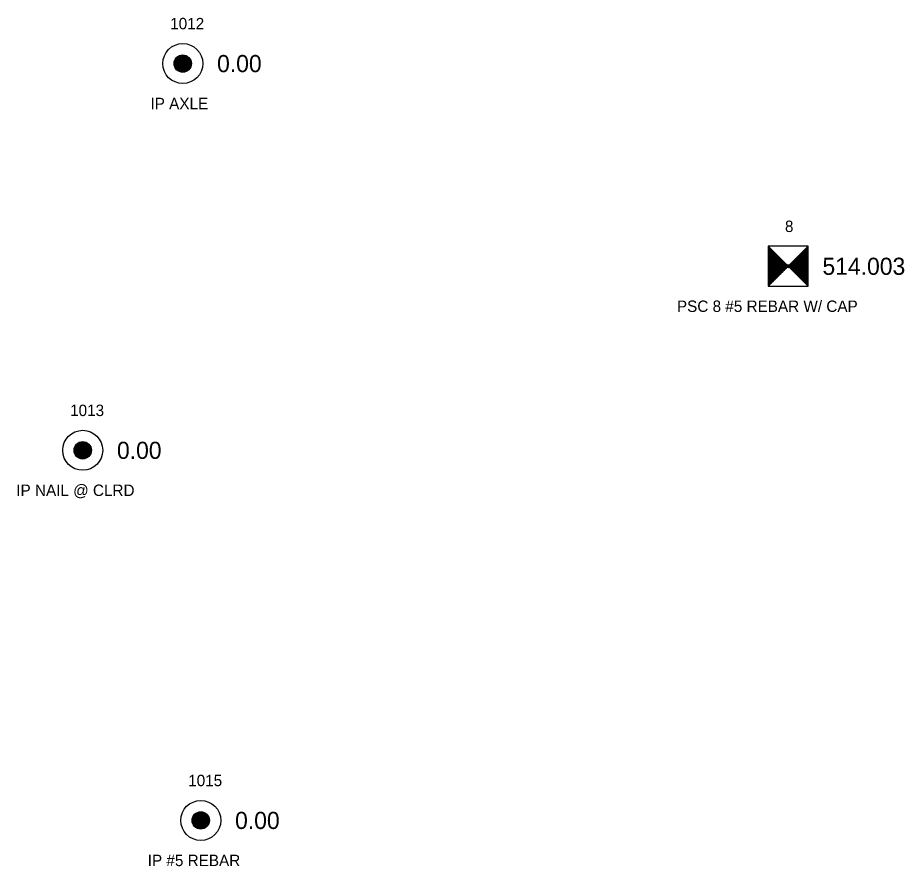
# Model space of a CAD drawing. Extents: x 1784103 to 1787401, y 770251 to 771298.
# Drawn here: x 1787322.9 to 1787400.5, y 770869.4 to 770943.7 of the extents above; entities that cross this region are included whole.
import ezdxf

# ---------------------------------------------------------------- set-up
doc = ezdxf.new("R2010")
doc.units = 0
for name, color, linetype in [('RD_EX_DV_Prop_txCode', 7, 'Continuous'), ('RD_EX_DV_PropPin', 7, 'Continuous'), ('RD_EX_TX_DV_Prop_ELEV', 7, 'Continuous'), ('RD_HC_Survey', 7, 'Continuous'), ('RD_HC_Survey_ELEV', 7, 'Continuous'), ('RD_HC_txCode', 7, 'Continuous'), ('RD_SMD_Locator', 7, 'Continuous')]:
    doc.layers.add(name, color=color, linetype=linetype)

msp = doc.modelspace()

# ---------------------------------------------------------------- linework, layer by layer
at = {"layer": 'RD_EX_DV_PropPin'}
for p, q in [((1787336.678, 770939.403), (1787336.678, 770939.999)), ((1787336.713, 770939.331), (1787336.713, 770940.07)), ((1787336.748, 770939.274), (1787336.748, 770940.127)), ((1787336.783, 770939.226), (1787336.783, 770940.175)), ((1787336.818, 770939.186), (1787336.818, 770940.216)), ((1787336.853, 770939.15), (1787336.853, 770940.251)), ((1787336.888, 770939.118), (1787336.888, 770940.283)), ((1787336.923, 770939.091), (1787336.923, 770940.31)), ((1787336.958, 770939.066), (1787336.958, 770940.335)), ((1787336.993, 770939.044), (1787336.993, 770940.357)), ((1787337.028, 770939.025), (1787337.028, 770940.376)), ((1787337.063, 770939.008), (1787337.063, 770940.393)), ((1787337.098, 770938.993), (1787337.098, 770940.408)), ((1787337.133, 770938.98), (1787337.133, 770940.421)), ((1787337.168, 770938.969), (1787337.168, 770940.432)), ((1787337.203, 770938.96), (1787337.203, 770940.441)), ((1787337.238, 770938.953), (1787337.238, 770940.449)), ((1787337.273, 770938.947), (1787337.273, 770940.454)), ((1787337.308, 770938.943), (1787337.308, 770940.458)), ((1787337.343, 770938.94), (1787337.343, 770940.461)), ((1787337.378, 770938.94), (1787337.378, 770940.462)), ((1787337.413, 770938.94), (1787337.413, 770940.461)), ((1787337.449, 770938.943), (1787337.449, 770940.458)), ((1787337.484, 770938.947), (1787337.484, 770940.454)), ((1787337.519, 770938.953), (1787337.519, 770940.449)), ((1787337.554, 770938.96), (1787337.554, 770940.441)), ((1787337.589, 770938.969), (1787337.589, 770940.432)), ((1787337.624, 770938.98), (1787337.624, 770940.421)), ((1787337.659, 770938.993), (1787337.659, 770940.408)), ((1787337.694, 770939.008), (1787337.694, 770940.393)), ((1787337.729, 770939.025), (1787337.729, 770940.376)), ((1787337.764, 770939.044), (1787337.764, 770940.357)), ((1787337.799, 770939.066), (1787337.799, 770940.335)), ((1787337.834, 770939.091), (1787337.834, 770940.31)), ((1787337.869, 770939.118), (1787337.869, 770940.283)), ((1787337.904, 770939.15), (1787337.904, 770940.251)), ((1787337.939, 770939.186), (1787337.939, 770940.216)), ((1787337.974, 770939.226), (1787337.974, 770940.175)), ((1787338.009, 770939.274), (1787338.009, 770940.127)), ((1787338.044, 770939.331), (1787338.044, 770940.07)), ((1787338.079, 770939.403), (1787338.079, 770939.999)), ((1787336.643, 770939.504), (1787336.643, 770939.897)), ((1787338.114, 770939.504), (1787338.114, 770939.897)), ((1787327.88, 770905.633), (1787327.88, 770906.025)), ((1787327.915, 770905.531), (1787327.915, 770906.127)), ((1787327.95, 770905.459), (1787327.95, 770906.198)), ((1787327.985, 770905.402), (1787327.985, 770906.255)), ((1787328.02, 770905.355), (1787328.02, 770906.303)), ((1787328.055, 770905.314), (1787328.055, 770906.344)), ((1787328.09, 770905.278), (1787328.09, 770906.379)), ((1787328.125, 770905.247), (1787328.125, 770906.411)), ((1787328.16, 770905.219), (1787328.16, 770906.439)), ((1787328.195, 770905.194), (1787328.195, 770906.463)), ((1787328.23, 770905.172), (1787328.23, 770906.485)), ((1787328.265, 770905.153), (1787328.265, 770906.504)), ((1787328.3, 770905.136), (1787328.3, 770906.521)), ((1787328.335, 770905.121), (1787328.335, 770906.536)), ((1787328.37, 770905.108), (1787328.37, 770906.549)), ((1787328.405, 770905.097), (1787328.405, 770906.56)), ((1787328.44, 770905.088), (1787328.44, 770906.569)), ((1787328.475, 770905.081), (1787328.475, 770906.577)), ((1787328.51, 770905.075), (1787328.51, 770906.582)), ((1787328.545, 770905.071), (1787328.545, 770906.586)), ((1787328.58, 770905.068), (1787328.58, 770906.589)), ((1787328.615, 770905.068), (1787328.615, 770906.59)), ((1787328.65, 770905.068), (1787328.65, 770906.589)), ((1787328.685, 770905.071), (1787328.685, 770906.586)), ((1787328.72, 770905.075), (1787328.72, 770906.582)), ((1787328.755, 770905.081), (1787328.755, 770906.577)), ((1787328.79, 770905.088), (1787328.79, 770906.569)), ((1787328.825, 770905.097), (1787328.825, 770906.56)), ((1787328.86, 770905.108), (1787328.86, 770906.549)), ((1787328.895, 770905.121), (1787328.895, 770906.536)), ((1787328.93, 770905.136), (1787328.93, 770906.521)), ((1787328.965, 770905.153), (1787328.965, 770906.504)), ((1787329, 770905.172), (1787329, 770906.485)), ((1787329.035, 770905.194), (1787329.035, 770906.463)), ((1787329.07, 770905.219), (1787329.07, 770906.439)), ((1787329.105, 770905.247), (1787329.105, 770906.411)), ((1787329.14, 770905.278), (1787329.14, 770906.379)), ((1787329.175, 770905.314), (1787329.175, 770906.344)), ((1787329.21, 770905.355), (1787329.21, 770906.303)), ((1787329.245, 770905.402), (1787329.245, 770906.255)), ((1787329.28, 770905.459), (1787329.28, 770906.198)), ((1787329.315, 770905.531), (1787329.315, 770906.127)), ((1787329.35, 770905.633), (1787329.35, 770906.025)), ((1787338.464, 770872.831), (1787338.464, 770873.995)), ((1787338.499, 770872.803), (1787338.499, 770874.023)), ((1787338.534, 770872.778), (1787338.534, 770874.048)), ((1787338.569, 770872.757), (1787338.569, 770874.069)), ((1787338.604, 770872.737), (1787338.604, 770874.089)), ((1787338.639, 770872.72), (1787338.639, 770874.106)), ((1787338.674, 770872.705), (1787338.674, 770874.121)), ((1787338.709, 770872.693), (1787338.709, 770874.133)), ((1787338.744, 770872.682), (1787338.744, 770874.144)), ((1787338.779, 770872.672), (1787338.779, 770874.154)), ((1787338.814, 770872.665), (1787338.814, 770874.161)), ((1787338.849, 770872.659), (1787338.849, 770874.167)), ((1787338.884, 770872.655), (1787338.884, 770874.171)), ((1787338.919, 770872.653), (1787338.919, 770874.173)), ((1787338.954, 770872.652), (1787338.954, 770874.174)), ((1787338.989, 770872.653), (1787338.989, 770874.173)), ((1787339.025, 770872.655), (1787339.025, 770874.171)), ((1787339.06, 770872.659), (1787339.06, 770874.167)), ((1787339.095, 770872.665), (1787339.095, 770874.161)), ((1787339.13, 770872.672), (1787339.13, 770874.154)), ((1787339.165, 770872.682), (1787339.165, 770874.144)), ((1787339.2, 770872.693), (1787339.2, 770874.133)), ((1787339.235, 770872.705), (1787339.235, 770874.121)), ((1787339.27, 770872.72), (1787339.27, 770874.106)), ((1787339.305, 770872.737), (1787339.305, 770874.089)), ((1787339.34, 770872.757), (1787339.34, 770874.069)), ((1787339.375, 770872.778), (1787339.375, 770874.048)), ((1787339.41, 770872.803), (1787339.41, 770874.023)), ((1787339.445, 770872.831), (1787339.445, 770873.995)), ((1787338.219, 770873.217), (1787338.219, 770873.609)), ((1787338.254, 770873.115), (1787338.254, 770873.711)), ((1787338.289, 770873.043), (1787338.289, 770873.783)), ((1787338.324, 770872.986), (1787338.324, 770873.84)), ((1787338.359, 770872.939), (1787338.359, 770873.887)), ((1787338.394, 770872.898), (1787338.394, 770873.928)), ((1787338.429, 770872.862), (1787338.429, 770873.964)), ((1787339.48, 770872.862), (1787339.48, 770873.964)), ((1787339.515, 770872.898), (1787339.515, 770873.928)), ((1787339.55, 770872.939), (1787339.55, 770873.887)), ((1787339.585, 770872.986), (1787339.585, 770873.84)), ((1787339.62, 770873.043), (1787339.62, 770873.783)), ((1787339.655, 770873.115), (1787339.655, 770873.711)), ((1787339.69, 770873.217), (1787339.69, 770873.609))]:
    msp.add_line(p, q, dxfattribs=at)
for centre, radius in [((1787337.378, 770939.701), 1.75), ((1787337.378, 770939.701), 0.761), ((1787328.615, 770905.829), 1.75), ((1787328.615, 770905.829), 0.761), ((1787338.954, 770873.413), 1.75), ((1787338.954, 770873.413), 0.761)]:
    msp.add_circle(centre, radius, dxfattribs=at)
at = {"layer": 'RD_HC_Survey'}
for p, q in [((1787388.629, 770923.698), (1787392.129, 770920.198)), ((1787392.129, 770923.698), (1787388.629, 770920.198)), ((1787388.654, 770923.673), (1787388.654, 770920.222)), ((1787392.105, 770923.673), (1787392.105, 770920.222)), ((1787388.679, 770923.648), (1787388.679, 770920.247)), ((1787388.704, 770923.623), (1787388.704, 770920.272)), ((1787388.728, 770923.599), (1787388.728, 770920.297)), ((1787388.753, 770923.574), (1787388.753, 770920.321)), ((1787388.778, 770923.549), (1787388.778, 770920.346)), ((1787388.803, 770923.524), (1787388.803, 770920.371)), ((1787388.827, 770923.5), (1787388.827, 770920.396)), ((1787388.852, 770923.475), (1787388.852, 770920.42)), ((1787388.877, 770923.45), (1787388.877, 770920.445)), ((1787388.902, 770923.425), (1787388.902, 770920.47)), ((1787388.926, 770923.401), (1787388.926, 770920.495)), ((1787388.951, 770923.376), (1787388.951, 770920.519)), ((1787388.976, 770923.351), (1787388.976, 770920.544)), ((1787389.001, 770923.326), (1787389.001, 770920.569)), ((1787389.025, 770923.302), (1787389.025, 770920.594)), ((1787389.05, 770923.277), (1787389.05, 770920.618)), ((1787389.075, 770923.252), (1787389.075, 770920.643)), ((1787389.1, 770923.227), (1787389.1, 770920.668)), ((1787389.124, 770923.203), (1787389.124, 770920.693)), ((1787389.149, 770923.178), (1787389.149, 770920.717)), ((1787389.174, 770923.153), (1787389.174, 770920.742)), ((1787389.199, 770923.128), (1787389.199, 770920.767)), ((1787389.223, 770923.104), (1787389.223, 770920.792)), ((1787389.248, 770923.079), (1787389.248, 770920.816)), ((1787389.273, 770923.054), (1787389.273, 770920.841)), ((1787389.298, 770923.029), (1787389.298, 770920.866)), ((1787389.322, 770923.005), (1787389.322, 770920.891)), ((1787389.347, 770922.98), (1787389.347, 770920.915)), ((1787389.372, 770922.955), (1787389.372, 770920.94)), ((1787389.397, 770922.93), (1787389.397, 770920.965)), ((1787389.421, 770922.906), (1787389.421, 770920.99)), ((1787391.337, 770922.906), (1787391.337, 770920.99)), ((1787391.362, 770922.93), (1787391.362, 770920.965)), ((1787391.387, 770922.955), (1787391.387, 770920.94)), ((1787391.412, 770922.98), (1787391.412, 770920.915)), ((1787391.436, 770923.005), (1787391.436, 770920.891)), ((1787391.461, 770923.029), (1787391.461, 770920.866)), ((1787391.486, 770923.054), (1787391.486, 770920.841)), ((1787391.511, 770923.079), (1787391.511, 770920.816)), ((1787391.535, 770923.104), (1787391.535, 770920.792)), ((1787391.56, 770923.128), (1787391.56, 770920.767)), ((1787391.585, 770923.153), (1787391.585, 770920.742)), ((1787391.61, 770923.178), (1787391.61, 770920.717)), ((1787391.634, 770923.203), (1787391.634, 770920.693)), ((1787391.659, 770923.227), (1787391.659, 770920.668)), ((1787391.684, 770923.252), (1787391.684, 770920.643)), ((1787391.709, 770923.277), (1787391.709, 770920.618)), ((1787391.733, 770923.302), (1787391.733, 770920.594)), ((1787391.758, 770923.326), (1787391.758, 770920.569)), ((1787391.783, 770923.351), (1787391.783, 770920.544)), ((1787391.808, 770923.376), (1787391.808, 770920.519)), ((1787391.832, 770923.401), (1787391.832, 770920.495)), ((1787391.857, 770923.425), (1787391.857, 770920.47)), ((1787391.882, 770923.45), (1787391.882, 770920.445)), ((1787391.907, 770923.475), (1787391.907, 770920.42)), ((1787391.931, 770923.5), (1787391.931, 770920.396)), ((1787391.956, 770923.524), (1787391.956, 770920.371)), ((1787391.981, 770923.549), (1787391.981, 770920.346)), ((1787392.006, 770923.574), (1787392.006, 770920.321)), ((1787392.03, 770923.599), (1787392.03, 770920.297)), ((1787392.055, 770923.623), (1787392.055, 770920.272)), ((1787392.08, 770923.648), (1787392.08, 770920.247)), ((1787389.446, 770922.881), (1787389.446, 770921.014)), ((1787389.471, 770922.856), (1787389.471, 770921.039)), ((1787389.496, 770922.831), (1787389.496, 770921.064)), ((1787389.52, 770922.807), (1787389.52, 770921.089)), ((1787389.545, 770922.782), (1787389.545, 770921.113)), ((1787389.57, 770922.757), (1787389.57, 770921.138)), ((1787389.595, 770922.732), (1787389.595, 770921.163)), ((1787389.619, 770922.708), (1787389.619, 770921.188)), ((1787389.644, 770922.683), (1787389.644, 770921.212)), ((1787389.669, 770922.658), (1787389.669, 770921.237)), ((1787389.693, 770922.633), (1787389.693, 770921.262)), ((1787389.718, 770922.609), (1787389.718, 770921.287)), ((1787389.743, 770922.584), (1787389.743, 770921.311)), ((1787389.768, 770922.559), (1787389.768, 770921.336)), ((1787389.792, 770922.534), (1787389.792, 770921.361)), ((1787389.817, 770922.51), (1787389.817, 770921.386)), ((1787389.842, 770922.485), (1787389.842, 770921.41)), ((1787389.867, 770922.46), (1787389.867, 770921.435)), ((1787389.891, 770922.435), (1787389.891, 770921.46)), ((1787389.916, 770922.411), (1787389.916, 770921.485)), ((1787389.941, 770922.386), (1787389.941, 770921.509)), ((1787389.966, 770922.361), (1787389.966, 770921.534)), ((1787389.99, 770922.336), (1787389.99, 770921.559)), ((1787390.015, 770922.312), (1787390.015, 770921.584)), ((1787390.04, 770922.287), (1787390.04, 770921.608)), ((1787390.065, 770922.262), (1787390.065, 770921.633)), ((1787390.089, 770922.237), (1787390.089, 770921.658)), ((1787390.114, 770922.213), (1787390.114, 770921.683)), ((1787390.139, 770922.188), (1787390.139, 770921.707)), ((1787390.164, 770922.163), (1787390.164, 770921.732)), ((1787390.188, 770922.138), (1787390.188, 770921.757)), ((1787390.213, 770922.114), (1787390.213, 770921.782)), ((1787390.545, 770922.114), (1787390.545, 770921.782)), ((1787390.57, 770922.138), (1787390.57, 770921.757)), ((1787390.595, 770922.163), (1787390.595, 770921.732)), ((1787390.62, 770922.188), (1787390.62, 770921.707)), ((1787390.644, 770922.213), (1787390.644, 770921.683)), ((1787390.669, 770922.237), (1787390.669, 770921.658)), ((1787390.694, 770922.262), (1787390.694, 770921.633)), ((1787390.719, 770922.287), (1787390.719, 770921.608)), ((1787390.743, 770922.312), (1787390.743, 770921.584)), ((1787390.768, 770922.336), (1787390.768, 770921.559)), ((1787390.793, 770922.361), (1787390.793, 770921.534)), ((1787390.818, 770922.386), (1787390.818, 770921.509)), ((1787390.842, 770922.411), (1787390.842, 770921.485)), ((1787390.867, 770922.435), (1787390.867, 770921.46)), ((1787390.892, 770922.46), (1787390.892, 770921.435)), ((1787390.917, 770922.485), (1787390.917, 770921.41)), ((1787390.941, 770922.51), (1787390.941, 770921.386)), ((1787390.966, 770922.534), (1787390.966, 770921.361)), ((1787390.991, 770922.559), (1787390.991, 770921.336)), ((1787391.016, 770922.584), (1787391.016, 770921.311)), ((1787391.04, 770922.609), (1787391.04, 770921.287)), ((1787391.065, 770922.633), (1787391.065, 770921.262)), ((1787391.09, 770922.658), (1787391.09, 770921.237)), ((1787391.115, 770922.683), (1787391.115, 770921.212)), ((1787391.139, 770922.708), (1787391.139, 770921.188)), ((1787391.164, 770922.732), (1787391.164, 770921.163)), ((1787391.189, 770922.757), (1787391.189, 770921.138)), ((1787391.214, 770922.782), (1787391.214, 770921.113)), ((1787391.238, 770922.807), (1787391.238, 770921.089)), ((1787391.263, 770922.831), (1787391.263, 770921.064)), ((1787391.288, 770922.856), (1787391.288, 770921.039)), ((1787391.313, 770922.881), (1787391.313, 770921.014)), ((1787390.238, 770922.089), (1787390.238, 770921.806)), ((1787390.263, 770922.064), (1787390.263, 770921.831)), ((1787390.287, 770922.039), (1787390.287, 770921.856)), ((1787390.312, 770922.015), (1787390.312, 770921.881)), ((1787390.337, 770921.99), (1787390.337, 770921.905)), ((1787390.362, 770921.965), (1787390.362, 770921.93)), ((1787390.397, 770921.965), (1787390.397, 770921.93)), ((1787390.422, 770921.99), (1787390.422, 770921.905)), ((1787390.446, 770922.015), (1787390.446, 770921.881)), ((1787390.471, 770922.039), (1787390.471, 770921.856)), ((1787390.496, 770922.064), (1787390.496, 770921.831)), ((1787390.521, 770922.089), (1787390.521, 770921.806))]:
    msp.add_line(p, q, dxfattribs=at)
msp.add_lwpolyline([(1787392.129, 770923.698), (1787388.629, 770923.698), (1787388.629, 770920.198), (1787392.129, 770920.198)], close=True, dxfattribs=at)
at = {"layer": 'RD_SMD_Locator'}
for centre in [(1787337.379, 770939.701), (1787390.379, 770921.948), (1787328.615, 770905.829), (1787338.955, 770873.413)]:
    msp.add_circle(centre, 0.15, dxfattribs=at)

# ---------------------------------------------------------------- texts
at = {"layer": 'RD_EX_DV_Prop_txCode'}
for s, p in [('1012', (1787336.276, 770942.701)), ('IP AXLE', (1787334.548, 770935.701)), ('1013', (1787327.513, 770908.829)), ('IP NAIL @ CLRD', (1787322.804, 770901.829)), ('1015', (1787337.852, 770876.413)), ('IP #5 REBAR', (1787334.309, 770869.413))]:
    msp.add_text(s, height=1, dxfattribs=at).set_placement(p)
at = {"layer": 'RD_EX_TX_DV_Prop_ELEV'}
for p in [(1787340.379, 770938.951), (1787331.615, 770905.079), (1787341.955, 770872.663)]:
    msp.add_text('0.00', height=1.5, dxfattribs=at).set_placement(p)
at = {"layer": 'RD_HC_Survey_ELEV'}
msp.add_text('514.003', height=1.5, dxfattribs=at).set_placement((1787393.379, 770921.198))
at = {"layer": 'RD_HC_txCode'}
for s, p in [('8', (1787390.096, 770924.948)), ('PSC 8 #5 REBAR W/ CAP', (1787380.639, 770917.948))]:
    msp.add_text(s, height=1, dxfattribs=at).set_placement(p)

doc.saveas('drawing.dxf')
